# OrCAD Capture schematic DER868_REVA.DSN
size C
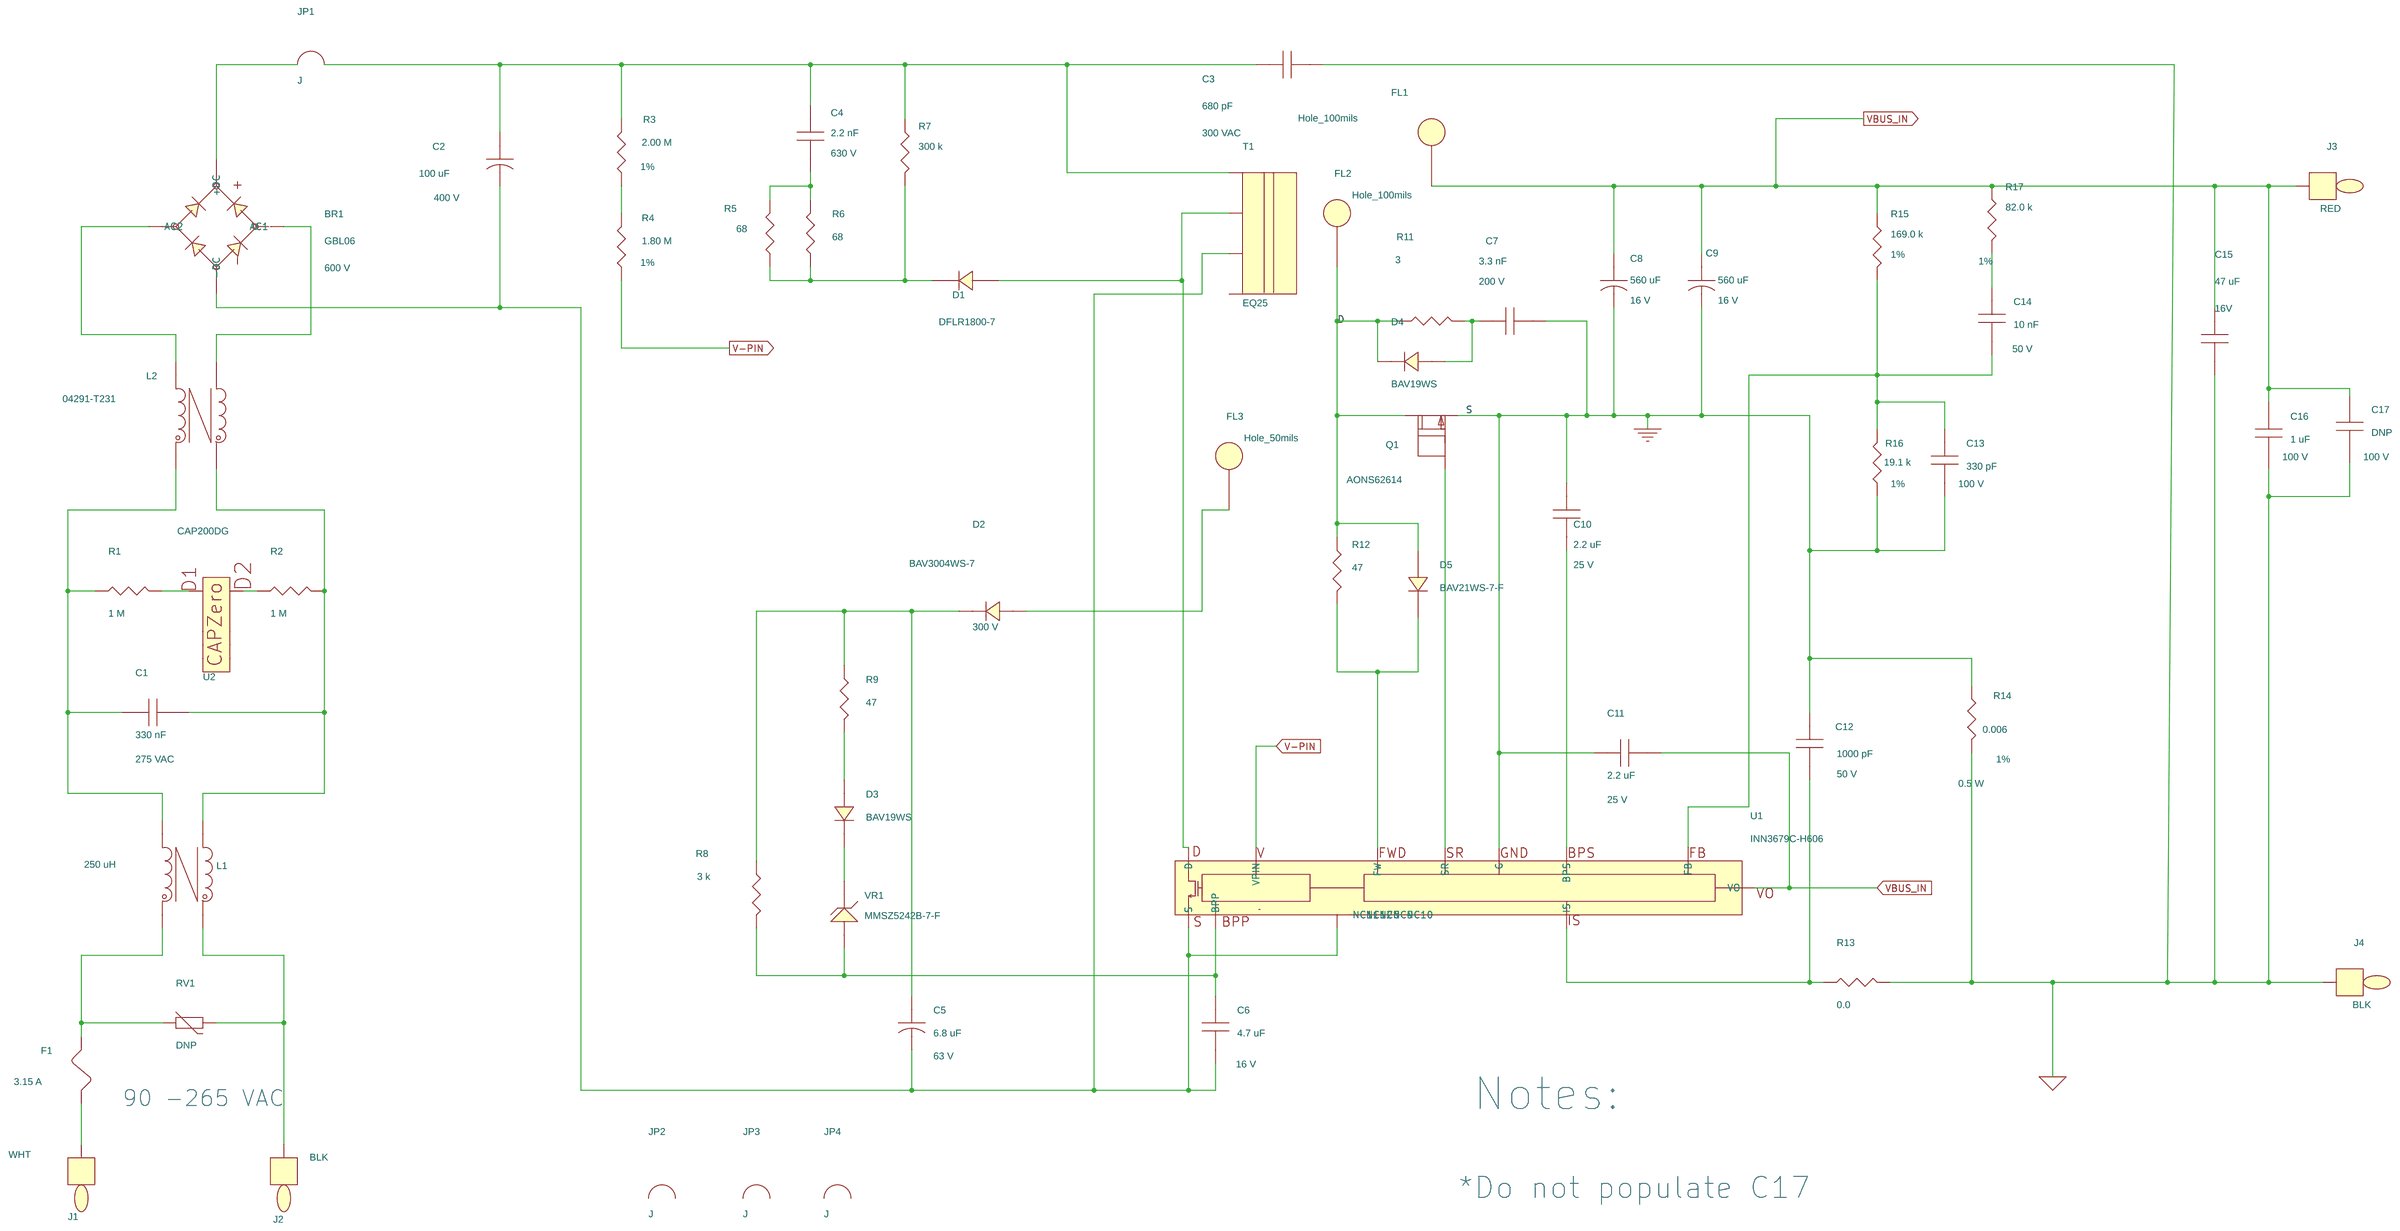
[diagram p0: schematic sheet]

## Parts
BR1  GBL06  [pidaxbridgegbl06]
C1  330 nF  [pinp_xcaprad15x8p5x14Hd040]
C2  100 uF  [pipolcapclyd630ls300040]
C3  680 pF  [pinpcaprad394x275394030]
C4  2.2 nF  [pismc1206]
C5  6.8 uF  [pipolcap4p0x11p0xls1p5d030]
C6  4.7 uF  [pismc0805]
C7  3.3 nF  [pismc0805]
C8  560 uF  [pipolcapclyd320ls140030]
C9  560 uF  [pipolcapclyd320ls140030]
C10  2.2 uF  [pismc0805]
C11  2.2 uF  [pismc1206]
C12  1000 pF  [pismr0402]
C13  330 pF  [pismc0402]
C14  10 nF  [pismr0402]
C15  47 uF  [pismc1206]
C16  1 uF  [pismc0805]
C17  DNP  [pismc0805]
D1  DFLR1800-7  [pismddflr120012]
D2  BAV3004WS-7  [pismsod323]
D3  BAV19WS  [pismsod323]
D4  BAV19WS  [pismsod323]
D5  BAV21WS-7-F  [pismsod323]
F1  3.15 A  [pi_rst_microfuse]
FL1  Hole_100mils  [pi_hole_100mil]
FL2  Hole_100mils  [pi_hole_100mil]
FL3  Hole_50mils  [pi_hole_50mil]
J1  WHT  [pitpkeystone125x125]
J2  BLK  [pitpkeystone125x125]
J3  RED  [pitpkeystone125x125]
J4  BLK  [pitpkeystone125x125]
JP1  J  [pi_jumper700]
JP2  J  [pi_jumper1000]
JP3  J  [pi_jumper500_d020]
JP4  J  [pi_jumper300_d020]
L1  250 uH  [pi_toroid_CMC4p_V_275uH]
L2  04291-T231  [pi_CMC_18mH_Sumida]
Q1  AONS62614  [pismpqfn5x6b]
R1  1 M  [pismr1206]
R2  1 M  [pismr1206]
R3  2.00 M  [pismr1206]
R4  1.80 M  [pismr1206]
R5  68  [pismr1206]
R6  68  [pismr1206]
R7  300 k  [pismr1206]
R8  3 k  [pismr0603]
R9  47  [pismr0603]
R11  3  [pismr0805]
R12  47  [pismr0603]
R13  0.0  [pismr0402]
R14  0.006  [pismr0805]
R15  169.0 k  [pismr0402]
R16  19.1 k  [pismr0402]
R17  82.0 k  [pismr0402]
RV1  DNP  [pidisc350x160ls210x140040]
T1  EQ25  [pi_bobbin_eq-2515p5_4p]
U1  INN3679C-H606  [pi_ic_insop_24d]
U2  CAP200DG  [pi_ic_smd_so8_capzero]
VR1  MMSZ5242B-7-F  [pi_sm_sod-123_12]

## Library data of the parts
BR1 = DISCRETE_BRIDGE_+~~-: Disp_Voltage: 600 V; Part Number: 15-01112-00; ROOM: 2
C1 = CAP_NP: ALT_SYMBOLS: pinp_xcaprad15x8p5x14Hd040H; Disp_Voltage: 275 VAC; FPLIST: pinp_xcaprad15x8p5x14Hd040,pinp_xcaprad15x8p5x14Hd040H; Part Number: 20-09095-00; ROOM: 2; Voltage: 275 VAC
C2 = CAP_POL: ALT_SYMBOLS: pipolcapclyd630ls3000401120h; COMPGROUP: 1; Disp_Voltage: 400 V; FPLIST: pipolcapclyd630ls300040,pipolcapclyd630ls3000401120h; Part Number: 20-00517-00; ROOM: 2; Voltage: 400 V
C3 = CAP_NP: ALT_SYMBOLS: pinpycaprad500x220ls400040; COMPGROUP: 3; Disp_Voltage: 300 VAC; FPLIST: pinpcaprad394x275394030,pinpycaprad500x220ls400040; PCB Editor PCBFP: pinpycaprad540x290ls400040; Part Number: 20-09027-00; ROOM: 2; Voltage: 300 VAC
C4 = CAP_NP_0: Disp_Voltage: 630 V; Part Number: 20-08609-00; ROOM: 2; Voltage: 630 V
C5 = CAP_POL: ALT_SYMBOLS: pipolcap4p0x11p0xls1p5d030h; Disp_Voltage: 63 V; FPLIST: pipolcap4p0x11p0xls1p5d030,pipolcap4p0x11p0xls1p5d030h; Part Number: 20-09108-00; ROOM: 2; Voltage: 63 V
C6 = CAP_NP: Disp_Voltage: 16 V; Part Number: 20-01390-00; ROOM: 2; Voltage: 16 V
C7 = CAP_NP: Disp_Voltage: 200 V; PCB Editor PCBFP: pismc0603; Part Number: 20-00956-00; ROOM: 2; Voltage: 200 V
C8 C9 = CAP_POL: ALT_SYMBOLS: pipolcapclyd320ls140030430h; Disp_Voltage: 16 V; FPLIST: pipolcapclyd320ls140030,pipolcapclyd320ls140030430h,pipolcapclyd320ls140030430h; Part Number: 20-09057-00; ROOM: 2; Voltage: 16 V
C10 = CAP_NP_0: Disp_Voltage: 25 V; Part Number: 20-08603-00; ROOM: 2; Voltage: 25 V
C11 = CAP_NP: Disp_Voltage: 25 V; Part Number: 20-01034-00; ROOM: 2; Voltage: 25 V
C12 = CAP_NP: ALT_SYMBOLS: pismr0402_1; Disp_Voltage: 50 V; FPLIST: pismr0402,pismr0402_1; Part Number: 20-09106-00; ROOM: 2; Voltage: 50 V
C13 = CAP_NP: ALT_SYMBOLS: pismr0402_1; Disp_Voltage: 100 V; FPLIST: pismc0402,pismr0402_1; Part Number: 20-09059-00; ROOM: 2; Voltage: 100 V
C14 = CAP_NP: Disp_Voltage: 50 V; Part Number: 20-09250-00; ROOM: 2; Voltage: 50 V
C15 = CAP_NP: Disp_Voltage: 16V; Part Number: 20-01116-00; ROOM: 2; Voltage: 16V
C16 C17 = CAP_NP: Disp_Voltage: 100 V; Part Number: 20-01324-00; ROOM: 2; Voltage: 100 V
D1 = DIODE: COMPGROUP: 2; Part Number: 15-00919-00; ROOM: 2
D2 = DIODE: COMPGROUP: 1; Disp_Voltage: 300 V; Part Number: 15-01138-00; ROOM: 2
D3 D4 = DIODE: Part Number: 15-00658-00; ROOM: 2
D5 = DIODE: Part Number: 15-00385-00
F1 = FUSE: ALT_SYMBOLS: pirstmicrofusehoz; COMPGROUP: 1; FPLIST: pi_rst_microfuse,pirstmicrofusehoz; Part Number: 40-00020-00; ROOM: 2
FL1 FL2 = FlyingLead: Part Number: 35-00432-00; ROOM: 2
FL3 = FlyingLead: Part Number: 35-00283-00; ROOM: 2
J1 = TESTPOINT: Part Number: 35-00044-00
J2 J4 = TESTPOINT: Part Number: 35-00042-00
J3 = TESTPOINT: Part Number: 35-00043-00
JP1 = JUMPER_1: Part Number: 65-00124-00; ROOM: 2
JP2 = JUMPER_1: Part Number: 65-00127-00; ROOM: 2
JP3 = JUMPER_1: Part Number: 65-00600-03; ROOM: 2
JP4 = JUMPER_1: Part Number: 65-00600-01; ROOM: 2
L1 = TORRID_4P_12_34: ALT_SYMBOLS: pi_toroid_CMC4p_V,pi_toroid_CMC4p_V_275uH; FPLIST: pi_toroid_CMC4p_H,pi_toroid_CMC4p_V,pi_toroid_CMC4p_V_275uH; Part Number: 32-00367-00; ROOM: 2
L2 = TORRID_4P_12_43a: Part Number: 30-00462-00; ROOM: 2
Q1 = FET_N_SGD_123_4_5678: Part Number: 50-00302-00; ROOM: 2
R1 R2 = R: Part Number: 05-01424-00; ROOM: 2
R3 = R: Disp_Tol: 1%; Part Number: 05-03156-00; ROOM: 2
R4 = R: Disp_Tol: 1%; Part Number: 05-03155-00; ROOM: 2
R5 R6 = R: Part Number: 05-01324-00; ROOM: 2
R7 = R: Part Number: 05-01411-00; ROOM: 2
R8 = R: Part Number: 05-01699-00; ROOM: 2
R9 R12 = R: Part Number: 05-01656-00; ROOM: 2
R11 = R: Part Number: 05-01458-00; ROOM: 2
R13 = R: Part Number: 05-06420-00; ROOM: 2
R14 = R: Disp_Power: 0.5 W; Disp_Tol: 1%; Part Number: 05-06516-00
R15 = R: Disp_Tol: 1%; Part Number: 05-06060-00; ROOM: 2
R16 = R: Disp_Tol: 1%; Part Number: 05-05964-00; ROOM: 2
R17 = R: Disp_Tol: 1%; Part Number: 05-06029-00; ROOM: 2
RV1 = VARISTOR: ALT_SYMBOLS: pi_disc_354x220_ls220x10_040_h; FPLIST: pidisc350x160ls210x140040,pi_disc_354x220_ls220x10_040_h; Part Number: 85-00015-00; ROOM: 2
T1 = BEQ2506_4P: Part Number: 25-01141-00
U1 = Inno3EP_0: Part Number: 10-01050-03
U2 = CAPZero: Part Number: 10-00958-00; ROOM: 2
VR1 = DIODE_ZENER: Part Number: 15-01090-00; ROOM: 2

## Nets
GND: C7.2 C8.2 C9.2 C10.1 C11.1 C12.1 C13.2 Q1.1(S) R14.1 R16.1 U1.2(G)
GND_SIGNAL: C3.2 C15.2 C16.2 C17.2 J4.1 R13.2 R14.2
VBUS_IN: C8.1 C9.1 C11.2 C15.1 C16.1 C17.1 FL1.1 J3.1 R15.1 R17.1 U1.6(VO)
D: D4.1 D5.2 FL2.1 Q1.5(D) R11.2 R12.1
NC8: U1.8(NC8)
NC9: U1.9(NC9)
NC10: U1.10(NC10)
NC11: U1.11(NC11)
NC12: U1.12(NC12)
V-PIN: R4.1 U1.13(VPIN)
N10479111: F1.1 J1.1
N10805923: BR1.4(-DC) C2.2 C5.2 C6.2 T1.3 U1.15 U1.16(S)
N10806149: C6.1 R8.2 U1.14(BPP) VR1.2
N10808843: C12.2 R13.1 U1.1(IS)
N10809540: Q1.4(G) U1.5(SR)
N10813018: R3.1 R4.2
N10840366: C2.1 C3.1 C4.1 JP1.2 R3.2 R7.1 T1.1
N10873526: D5.1 R12.2 U1.7(FW)
N10897256: C13.1 C14.2 R15.2 R16.2 U1.3(FB)
N10950053: C5.1 D2.1 R8.1 R9.1
N10966650: D1.2 T1.2 U1.24(D)
N11058959: BR1.1(+DC) JP1.1
N11077448: D3.2 R9.2
N11099981: C1.1 L1.2 L2.1 R1.1
N11100013: C1.2 L1.4 L2.4 R2.2
N11100021: BR1.3(AC2) L2.2
N11100037: BR1.2(AC1) L2.3
N11105885: D2.2 FL3.1
N11139529: D1.1 R5.1 R6.1 R7.2
N11139619: C4.2 R5.2 R6.2
N11156493: C7.1 D4.2 R11.1
N11376588: F1.2 L1.1 RV1.1
N11376604: J2.1 L1.3 RV1.2
N11381159: R1.2 U2.2(D1)
N11473834: D3.1 VR1.1
N11479585: C14.1 R17.2
N11508957: R2.1 U2.7(D2)
N11512145: C10.2 U1.4(BPS)

Not connected (* = marked no-connect by the designer): JP2 1 2; JP3 1 2; JP4 1 2; Q1 2(S2) 3(S3) 6(D6) 7(D7) 8(D8); T1 4; U2 1(NC1) 3(NC2) 4(NC3) 5(NC4) 6(NC5) 8(NC8)

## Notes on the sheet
- Notes:
- 90 -265 VAC
- *Do not populate C17
